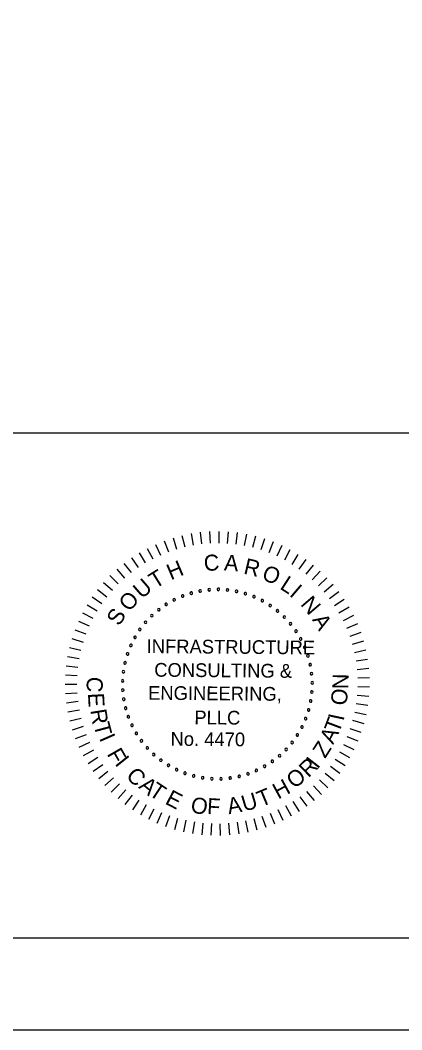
# Model space of a CAD drawing. Extents: x -50.5 to -14.4, y 42.4 to 64.4.
# Drawn here: x -25.26 to -23.18, y 42.45 to 47.94 of the extents above; entities that cross this region are included whole.
import ezdxf

# ---------------------------------------------------------------- set-up
doc = ezdxf.new("R2010")
doc.units = 0
for name, color, linetype in [('BR_BORDER LINES', 7, 'Continuous'), ('BR_TEXT', 7, 'Continuous'), ('Level 31', 7, 'Continuous')]:
    doc.layers.add(name, color=color, linetype=linetype)

msp = doc.modelspace()

# ---------------------------------------------------------------- linework, layer by layer
at = {"layer": 'BR_BORDER LINES'}
for p, q in [((-27.8847, 45.6987), (-22.5195, 45.6987)), ((-48.6853, 42.9486), (-15.0192, 42.9486))]:
    msp.add_line(p, q, dxfattribs=at)
at = {"layer": 'BR_TEXT'}
for p, q in [((-24.427, 45.1262), (-24.4084, 45.0653)), ((-24.3783, 45.1394), (-24.3634, 45.0775)), ((-24.3289, 45.1496), (-24.3178, 45.0869)), ((-24.2789, 45.1568), (-24.2717, 45.0935)), ((-24.2286, 45.1609), (-24.2252, 45.0974)), ((-24.1781, 45.162), (-24.1786, 45.0983)), ((-24.1277, 45.16), (-24.1321, 45.0965)), ((-24.0774, 45.1549), (-24.0857, 45.0918)), ((-24.0276, 45.1468), (-24.0397, 45.0842)), ((-23.9784, 45.1356), (-23.9943, 45.0739)), ((-23.9299, 45.1214), (-23.9495, 45.0609)), ((-24.5671, 45.0691), (-24.5377, 45.0126)), ((-24.5216, 45.0909), (-24.4957, 45.0328)), ((-24.4748, 45.11), (-24.4525, 45.0504)), ((-23.8824, 45.1044), (-23.9057, 45.0451)), ((-23.836, 45.0844), (-23.8629, 45.0267)), ((-24.6537, 45.0172), (-24.6176, 44.9647)), ((-24.6112, 45.0445), (-24.5784, 44.9899)), ((-23.7909, 45.0617), (-23.8213, 45.0057)), ((-23.7473, 45.0363), (-23.781, 44.9822)), ((-24.7333, 44.9552), (-24.6911, 44.9075)), ((-24.6944, 44.9874), (-24.6553, 44.9372)), ((-23.7054, 45.0082), (-23.7423, 44.9563)), ((-23.6652, 44.9777), (-23.7052, 44.9281)), ((-24.7701, 44.9207), (-24.7251, 44.8756)), ((-23.6269, 44.9447), (-23.6699, 44.8977)), ((-23.5907, 44.9095), (-23.6365, 44.8652)), ((-24.8372, 44.8452), (-24.787, 44.806)), ((-24.8048, 44.884), (-24.7571, 44.8418)), ((-23.5568, 44.8722), (-23.6051, 44.8307)), ((-24.8671, 44.8046), (-24.8147, 44.7685)), ((-23.5252, 44.8328), (-23.576, 44.7944)), ((-23.496, 44.7916), (-23.549, 44.7564)), ((-24.8945, 44.7622), (-24.84, 44.7293)), ((-23.4694, 44.7487), (-23.5245, 44.7167)), ((-24.9193, 44.7182), (-24.8628, 44.6887)), ((-23.4455, 44.7042), (-23.5024, 44.6757)), ((-24.9605, 44.6261), (-24.9009, 44.6037)), ((-24.9413, 44.6728), (-24.8832, 44.6468)), ((-23.4243, 44.6584), (-23.4829, 44.6334)), ((-24.9769, 44.5783), (-24.916, 44.5596)), ((-23.406, 44.6114), (-23.466, 44.59)), ((-24.9903, 44.5297), (-24.9284, 44.5147)), ((-23.3905, 44.5633), (-23.4517, 44.5456)), ((-25.0007, 44.4803), (-24.938, 44.4691)), ((-23.3781, 44.5144), (-23.4402, 44.5005)), ((-23.3686, 44.4648), (-23.4315, 44.4547)), ((-25.0081, 44.4303), (-24.9448, 44.423)), ((-23.3622, 44.4147), (-23.4255, 44.4085)), ((-25.0124, 44.38), (-24.9488, 44.3766)), ((-23.3588, 44.3644), (-23.4224, 44.362)), ((-25.0136, 44.3296), (-24.95, 44.33)), ((-23.3585, 44.3139), (-23.4221, 44.3154)), ((-25.0118, 44.2791), (-24.9483, 44.2834)), ((-23.3613, 44.2635), (-23.4247, 44.2688)), ((-25.0069, 44.2289), (-24.9438, 44.2371)), ((-24.999, 44.179), (-24.9364, 44.191)), ((-23.3671, 44.2133), (-23.4301, 44.2226)), ((-24.988, 44.1297), (-24.9263, 44.1455)), ((-23.388, 44.1146), (-23.4494, 44.1314)), ((-23.376, 44.1636), (-23.4384, 44.1767)), ((-24.974, 44.0812), (-24.9134, 44.1008)), ((-23.4028, 44.0663), (-23.4631, 44.0869)), ((-24.9571, 44.0336), (-24.8978, 44.0569)), ((-23.4206, 44.0191), (-23.4795, 44.0433)), ((-24.9373, 43.9872), (-24.8796, 44.014)), ((-24.9148, 43.942), (-24.8588, 43.9723)), ((-23.4413, 43.973), (-23.4986, 44.0007)), ((-24.8895, 43.8983), (-24.8354, 43.9319)), ((-23.4908, 43.8851), (-23.5443, 43.9196)), ((-23.4647, 43.9283), (-23.5202, 43.9595)), ((-24.8616, 43.8563), (-24.8097, 43.8931)), ((-24.8312, 43.8159), (-24.7816, 43.8559)), ((-23.5195, 43.8435), (-23.5708, 43.8812)), ((-24.7984, 43.7776), (-24.7514, 43.8205)), ((-23.5841, 43.7661), (-23.6305, 43.8097)), ((-23.5506, 43.8038), (-23.5995, 43.8446)), ((-24.7633, 43.7413), (-24.719, 43.7869)), ((-24.7261, 43.7072), (-24.6846, 43.7555)), ((-23.6578, 43.697), (-23.6985, 43.746)), ((-23.6199, 43.7304), (-23.6635, 43.7768)), ((-24.6869, 43.6754), (-24.6484, 43.7261)), ((-24.6458, 43.6461), (-24.6105, 43.6991)), ((-23.7393, 43.6375), (-23.7737, 43.6911)), ((-23.6976, 43.666), (-23.7352, 43.7174)), ((-24.603, 43.6193), (-24.5709, 43.6744)), ((-24.5586, 43.5953), (-24.53, 43.6521)), ((-23.8274, 43.5883), (-23.855, 43.6457)), ((-23.7826, 43.6116), (-23.8137, 43.6671)), ((-24.5128, 43.5739), (-24.4878, 43.6324)), ((-24.4659, 43.5554), (-24.4444, 43.6153)), ((-24.4179, 43.5398), (-24.4001, 43.6009)), ((-24.369, 43.5271), (-24.355, 43.5892)), ((-24.0182, 43.5238), (-24.0312, 43.5861)), ((-23.9691, 43.5355), (-23.9859, 43.597)), ((-23.9208, 43.5502), (-23.9413, 43.6105)), ((-23.8735, 43.5679), (-23.8976, 43.6268)), ((-24.3194, 43.5175), (-24.3092, 43.5803)), ((-24.2694, 43.5108), (-24.2631, 43.5742)), ((-24.219, 43.5073), (-24.2166, 43.5709)), ((-24.1686, 43.5068), (-24.17, 43.5705)), ((-24.1181, 43.5094), (-24.1234, 43.5729)), ((-24.068, 43.5151), (-24.0771, 43.5781))]:
    msp.add_line(p, q, dxfattribs=at)
for centre, start, end in [((-24.2303, 44.844), 5.0653, 185.0653), ((-24.1805, 44.8459), 359.5268, 179.5268), ((-24.1805, 44.8459), 179.5268, 359.5268), ((-24.1308, 44.8429), 353.9884, 173.9884), ((-24.4208, 44.7892), 27.2191, 207.2191), ((-24.4208, 44.7892), 207.2191, 27.2191), ((-24.3754, 44.8098), 21.6807, 201.6807), ((-24.3754, 44.8098), 201.6807, 21.6807), ((-24.3282, 44.8258), 16.1422, 196.1422), ((-24.3282, 44.8258), 196.1422, 16.1422), ((-24.2797, 44.8373), 10.6038, 190.6038), ((-24.2797, 44.8373), 190.6038, 10.6038), ((-24.2303, 44.844), 185.0653, 5.0653), ((-24.1308, 44.8429), 173.9884, 353.9884), ((-24.0816, 44.8352), 168.4499, 348.4499), ((-24.0816, 44.8352), 348.4499, 168.4499), ((-24.0333, 44.8228), 162.9114, 342.9114), ((-24.0333, 44.8228), 342.9114, 162.9114), ((-23.9865, 44.8058), 157.373, 337.373), ((-23.9865, 44.8058), 337.373, 157.373), ((-23.9415, 44.7843), 331.8345, 151.8345), ((-24.5046, 44.7355), 38.2961, 218.2961), ((-24.5046, 44.7355), 218.2961, 38.2961), ((-24.464, 44.7644), 32.7576, 212.7576), ((-24.464, 44.7644), 212.7576, 32.7576), ((-23.9415, 44.7843), 151.8345, 331.8345), ((-23.8988, 44.7586), 146.2961, 326.2961), ((-23.8988, 44.7586), 326.2961, 146.2961), ((-23.8588, 44.7289), 320.7576, 140.7576), ((-24.5422, 44.7029), 43.8345, 223.8345), ((-24.5422, 44.7029), 223.8345, 43.8345), ((-23.8588, 44.7289), 140.7576, 320.7576), ((-23.8218, 44.6955), 135.2191, 315.2191), ((-23.8218, 44.6955), 315.2191, 135.2191), ((-24.6072, 44.6275), 54.9114, 234.9114), ((-24.6072, 44.6275), 234.9114, 54.9114), ((-24.5765, 44.6667), 49.373, 229.373), ((-24.5765, 44.6667), 229.373, 49.373), ((-23.7883, 44.6587), 129.6807, 309.6807), ((-23.7883, 44.6587), 309.6807, 129.6807), ((-23.7584, 44.6188), 304.1422, 124.1422), ((-24.6339, 44.5854), 60.4499, 240.4499), ((-24.6339, 44.5854), 240.4499, 60.4499), ((-23.7584, 44.6188), 124.1422, 304.1422), ((-23.7326, 44.5762), 118.6038, 298.6038), ((-23.7326, 44.5762), 298.6038, 118.6038), ((-24.6565, 44.541), 65.9884, 245.9884), ((-24.6565, 44.541), 245.9884, 65.9884), ((-23.7109, 44.5313), 113.0653, 293.0653), ((-23.7109, 44.5313), 293.0653, 113.0653), ((-24.6746, 44.4946), 71.5268, 251.5268), ((-24.6746, 44.4946), 251.5268, 71.5268), ((-23.6937, 44.4845), 107.5268, 287.5268), ((-23.6937, 44.4845), 287.5268, 107.5268), ((-24.6882, 44.4466), 77.0653, 257.0653), ((-24.6882, 44.4466), 257.0653, 77.0653), ((-23.6812, 44.4363), 101.9884, 281.9884), ((-23.6812, 44.4363), 281.9884, 101.9884), ((-24.7012, 44.3479), 88.1422, 268.1422), ((-24.6971, 44.3976), 82.6038, 262.6038), ((-24.7012, 44.3479), 268.1422, 88.1422), ((-24.6971, 44.3976), 262.6038, 82.6038), ((-23.6733, 44.3871), 96.4499, 276.4499), ((-23.6733, 44.3871), 276.4499, 96.4499), ((-24.7005, 44.2981), 93.6807, 273.6807), ((-24.7005, 44.2981), 273.6807, 93.6807), ((-23.6702, 44.3374), 90.9114, 270.9114), ((-23.6702, 44.3374), 270.9114, 90.9114), ((-24.695, 44.2486), 99.2191, 279.2191), ((-24.695, 44.2486), 279.2191, 99.2191), ((-23.6784, 44.2382), 79.8345, 259.8345), ((-23.6784, 44.2382), 259.8345, 79.8345), ((-23.6719, 44.2876), 85.373, 265.373), ((-23.6719, 44.2876), 265.373, 85.373), ((-24.6848, 44.1998), 104.7576, 284.7576), ((-24.6848, 44.1998), 284.7576, 104.7576), ((-23.6896, 44.1896), 74.2961, 254.2961), ((-23.6896, 44.1896), 254.2961, 74.2961), ((-24.6699, 44.1523), 110.2961, 290.2961), ((-24.6699, 44.1523), 290.2961, 110.2961), ((-23.7055, 44.1424), 68.7576, 248.7576), ((-23.7055, 44.1424), 248.7576, 68.7576), ((-24.6504, 44.1064), 115.8345, 295.8345), ((-24.6504, 44.1064), 295.8345, 115.8345), ((-23.7259, 44.0969), 63.2191, 243.2191), ((-23.7259, 44.0969), 243.2191, 63.2191), ((-24.6267, 44.0626), 121.373, 301.373), ((-24.6267, 44.0626), 301.373, 121.373), ((-24.5988, 44.0213), 126.9114, 306.9114), ((-24.5988, 44.0213), 306.9114, 126.9114), ((-23.7506, 44.0536), 57.6807, 237.6807), ((-23.7506, 44.0536), 237.6807, 57.6807), ((-24.567, 43.9829), 132.4499, 312.4499), ((-24.567, 43.9829), 312.4499, 132.4499), ((-23.8118, 43.9751), 46.6038, 226.6038), ((-23.8118, 43.9751), 226.6038, 46.6038), ((-23.7793, 44.0129), 52.1422, 232.1422), ((-23.7793, 44.0129), 232.1422, 52.1422), ((-24.5317, 43.9477), 137.9884, 317.9884), ((-24.5317, 43.9477), 317.9884, 137.9884), ((-24.4932, 43.9161), 143.5268, 323.5268), ((-24.4932, 43.9161), 323.5268, 143.5268), ((-23.887, 43.9099), 35.5268, 215.5268), ((-23.887, 43.9099), 215.5268, 35.5268), ((-23.8478, 43.9407), 41.0653, 221.0653), ((-23.8478, 43.9407), 221.0653, 41.0653), ((-24.4518, 43.8884), 149.0653, 329.0653), ((-24.4518, 43.8884), 329.0653, 149.0653), ((-24.4079, 43.8648), 154.6038, 334.6038), ((-24.4079, 43.8648), 334.6038, 154.6038), ((-23.9733, 43.8603), 24.4499, 204.4499), ((-23.9733, 43.8603), 204.4499, 24.4499), ((-23.9289, 43.883), 29.9884, 209.9884), ((-23.9289, 43.883), 209.9884, 29.9884), ((-24.362, 43.8455), 160.1422, 340.1422), ((-24.362, 43.8455), 340.1422, 160.1422), ((-24.3144, 43.8308), 165.6807, 345.6807), ((-24.3144, 43.8308), 345.6807, 165.6807), ((-24.2656, 43.8207), 171.2191, 351.2191), ((-24.2656, 43.8207), 351.2191, 171.2191), ((-24.216, 43.8154), 356.7576, 176.7576), ((-24.216, 43.8154), 176.7576, 356.7576), ((-24.1662, 43.8148), 2.2961, 182.2961), ((-24.1662, 43.8148), 182.2961, 2.2961), ((-24.1165, 43.8192), 7.8345, 187.8345), ((-24.1165, 43.8192), 187.8345, 7.8345), ((-24.0675, 43.8282), 13.373, 193.373), ((-24.0675, 43.8282), 193.373, 13.373), ((-24.0196, 43.842), 18.9114, 198.9114), ((-24.0196, 43.842), 198.9114, 18.9114)]:
    msp.add_arc(centre, 0.00701, start, end, dxfattribs=at)
at = {"layer": 'Level 31'}
msp.add_lwpolyline([(-50.5186, 42.4486), (-14.5186, 42.4486), (-14.5186, 64.4486), (-50.5186, 64.4486)], close=True, dxfattribs=at)

# ---------------------------------------------------------------- texts
at = {"layer": 'BR_TEXT'}
for s, height, rotation, p in [('C', 0.0872, 4.7281, (-24.256, 44.9444)), ('A', 0.0872, 355.6981, (-24.1516, 44.9494)), ('R', 0.0872, 346.6681, (-24.0473, 44.9324)), ('T', 0.0872, 31.8182, (-24.5237, 44.8474)), ('H', 0.0872, 22.7882, (-24.4389, 44.895)), ('O', 0.0872, 337.638, (-23.9496, 44.9026)), ('U', 0.0872, 40.8482, (-24.597, 44.7912)), ('L', 0.0872, 327.108, (-23.8507, 44.8521)), ('I', 0.0872, 319.578, (-23.7982, 44.8143)), ('O', 0.0872, 49.8782, (-24.664, 44.7202)), ('N', 0.0872, 310.548, (-23.7373, 44.7635)), ('S', 0.0872, 58.9083, (-24.7194, 44.6421)), ('A', 0.0872, 301.5179, (-23.6723, 44.6811)), ('INFRASTRUCTURE', 0.074771, 359.5268, (-24.5708, 44.4995)), ('CONSULTING &', 0.074771, 359.5268, (-24.5295, 44.3709)), ('C', 0.0872, 267.025, (-24.8944, 44.3721)), ('N', 0.0872, 89.2085, (-23.473, 44.3024)), ('ENGINEERING,', 0.074771, 359.5268, (-24.5631, 44.2455)), ('O', 0.0872, 83.2085, (-23.4841, 44.2109)), ('E', 0.0872, 273.025, (-24.89, 44.2805)), ('R', 0.0872, 279.025, (-24.8773, 44.1883)), ('PLLC', 0.07477, 359.5268, (-24.3114, 44.1119)), ('T', 0.0872, 69.3954, (-23.5253, 44.0591)), ('I', 0.0872, 77.9093, (-23.4996, 44.1266)), ('T', 0.0872, 285.025, (-24.8599, 44.1095)), ('A', 0.0872, 63.3954, (-23.5561, 43.9988)), ('I', 0.0872, 293.7713, (-24.8302, 44.0364)), ('No. 4470', 0.07477, 359.5268, (-24.441, 43.995)), ('Z', 0.0872, 57.3954, (-23.5999, 43.9224)), ('F', 0.0872, 299.7713, (-24.789, 43.9503)), ('I', 0.0872, 308.5268, (-24.7469, 43.8965)), ('R', 0.0872, 44.5268, (-23.6904, 43.8175)), ('I', 0.0872, 52.3339, (-23.641, 43.8648)), ('C', 0.0872, 314.5268, (-24.6875, 43.8264)), ('O', 0.0872, 38.5268, (-23.7669, 43.7575)), ('A', 0.0872, 320.5268, (-24.6184, 43.7678)), ('T', 0.0872, 326.5268, (-24.5639, 43.7293)), ('H', 0.0872, 28.5268, (-23.855, 43.7015)), ('E', 0.0872, 332.5268, (-24.4753, 43.6815)), ('T', 0.0872, 22.5268, (-23.9482, 43.6597)), ('O', 0.0872, 350.5268, (-24.3352, 43.6326)), ('F', 0.0872, 356.5268, (-24.2437, 43.6235)), ('A', 0.0872, 10.5268, (-24.1239, 43.6219)), ('U', 0.0872, 16.5268, (-24.04, 43.6354))]:
    msp.add_text(s, height=height, rotation=rotation, dxfattribs=at).set_placement(p)

doc.saveas('drawing.dxf')
